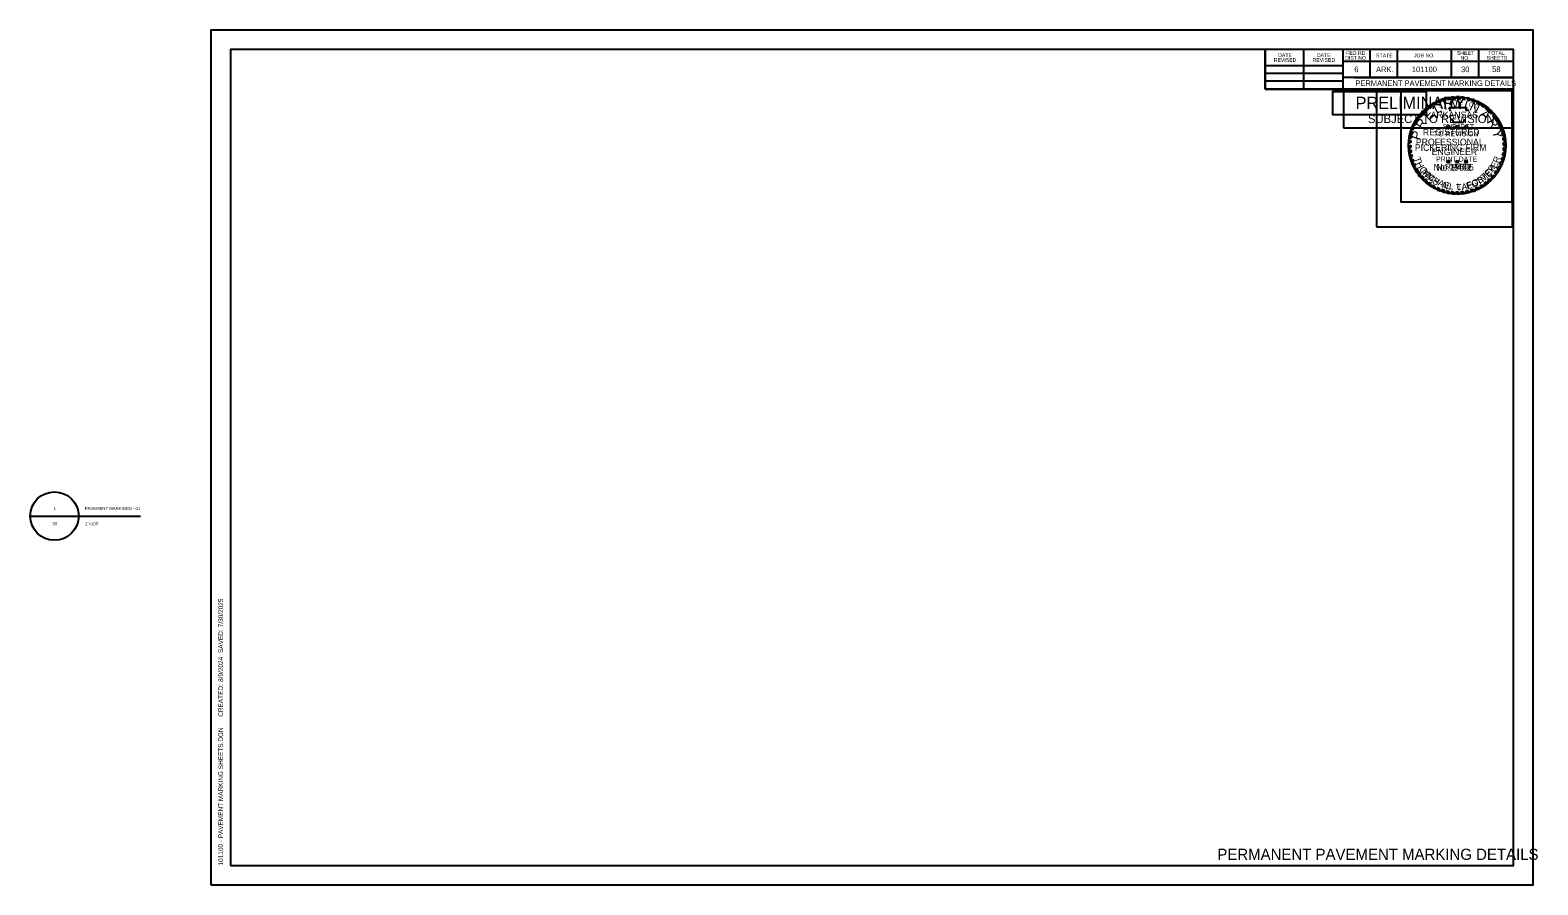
# Model space of a CAD drawing. Extents: x -0.19 to 1.42, y 0 to 0.92.
import ezdxf

# ---------------------------------------------------------------- set-up
doc = ezdxf.new("R2010")
doc.units = 0
for name, color, linetype in [('Default', 7, 'Continuous'), ('DSN_DRFT_Guideline-No-Plot', 7, 'Continuous'), ('SHET_Annotations', 7, 'Continuous'), ('SHET_Border-Lines', 7, 'Continuous'), ('SHET_Border-Text', 7, 'Continuous'), ('SHET_Stamp-Prelim', 7, 'Continuous'), ('SHET_Stamp-Seal', 7, 'Continuous'), ('STAMP_PE DIG SIG', 7, 'Continuous'), ('STAMP_PE_BACKGROUND', 7, 'Continuous'), ('STAMP_PE_FOSTER', 7, 'Continuous'), ('STAMP_PE_SEAL-INFO', 7, 'Continuous'), ('STAMP_PE_TAEGTMEYER', 7, 'Continuous'), ('STAMP_PRELIMINARY', 7, 'Continuous')]:
    doc.layers.add(name, color=color, linetype=linetype)

msp = doc.modelspace()

# ---------------------------------------------------------------- linework, layer by layer
at = {"layer": 'Default'}
for p, q in [((-0.1938, 0.3955), (-0.1417, 0.3955)), ((-0.1675, 0.3955), (-0.0755, 0.3955))]:
    msp.add_line(p, q, dxfattribs=at)
msp.add_circle((-0.1677, 0.3955), 0.026, dxfattribs=at)
at = {"layer": 'DSN_DRFT_Guideline-No-Plot'}
msp.add_lwpolyline([(0, 0), (1.4167, 0), (1.4167, 0.9167), (0, 0.9167)], close=True, dxfattribs=at)
at = {"layer": 'SHET_Border-Lines'}
for p, q in [((0.1176, 0.8988), (0.1176, 0.8988)), ((0.1176, 0.8988), (0.1176, 0.8988)), ((1.1296, 0.8534), (1.1296, 0.8958)), ((1.1711, 0.8534), (1.1711, 0.8958)), ((1.2127, 0.8958), (1.2127, 0.8534)), ((1.2417, 0.8958), (1.2417, 0.866)), ((1.2712, 0.8958), (1.2712, 0.866)), ((1.3289, 0.8958), (1.3289, 0.866)), ((1.3584, 0.8958), (1.3584, 0.866)), ((1.1296, 0.8786), (1.2127, 0.8786)), ((1.3958, 0.8832), (1.2127, 0.8832)), ((1.3958, 0.8833), (1.3958, 0.8833)), ((1.1296, 0.8706), (1.2127, 0.8706)), ((1.1296, 0.8622), (1.2127, 0.8622)), ((1.3958, 0.866), (1.2127, 0.866)), ((1.2252, 0.866), (1.3958, 0.866)), ((1.3958, 0.8534), (1.1296, 0.8534))]:
    msp.add_line(p, q, dxfattribs=at)
for points in [[(0.0208, 0.0208), (1.3958, 0.0208), (1.3958, 0.8958), (0.0208, 0.8958)], [(1.1296, 0.8534), (1.3958, 0.8534), (1.3958, 0.8958), (1.1296, 0.8958)]]:
    msp.add_lwpolyline(points, close=True, dxfattribs=at)
at = {"layer": 'SHET_Stamp-Prelim'}
msp.add_lwpolyline([(1.2137, 0.8119), (1.3948, 0.8119), (1.3948, 0.8524), (1.2137, 0.8524)], close=True, dxfattribs=at)
at = {"layer": 'SHET_Stamp-Seal'}
msp.add_line((1.3219, 0.7895), (1.3219, 0.7895), dxfattribs=at)
msp.add_lwpolyline([(1.249, 0.7057), (1.3948, 0.7057), (1.3948, 0.8524), (1.249, 0.8524)], close=True, dxfattribs=at)
at = {"layer": 'STAMP_PE DIG SIG'}
msp.add_lwpolyline([(1.2022, 0.8508), (1.3022, 0.8508), (1.3022, 0.8258), (1.2022, 0.8258)], close=True, dxfattribs=at)
at = {"layer": 'STAMP_PE_BACKGROUND'}
for points in [[(1.2022, 0.8517), (1.3022, 0.8517), (1.3022, 0.8258), (1.2022, 0.8258)], [(1.3942, 0.8517), (1.275, 0.8517), (1.275, 0.7325), (1.3942, 0.7325)]]:
    msp.add_lwpolyline(points, close=True, dxfattribs=at)
at = {"layer": 'STAMP_PE_SEAL-INFO'}
for p, q in [((1.3137, 0.8403), (1.3158, 0.8387)), ((1.3165, 0.8415), (1.3181, 0.8397)), ((1.3184, 0.8422), (1.3206, 0.8405)), ((1.3217, 0.8432), (1.3233, 0.8413)), ((1.3239, 0.8438), (1.3259, 0.8418)), ((1.3266, 0.8443), (1.3283, 0.8422)), ((1.3295, 0.8447), (1.331, 0.8426)), ((1.3336, 0.8427), (1.3318, 0.8449)), ((1.3364, 0.8428), (1.3348, 0.845)), ((1.3389, 0.8426), (1.3375, 0.845)), ((1.3417, 0.8424), (1.3401, 0.8448)), ((1.3441, 0.842), (1.3427, 0.8445)), ((1.3473, 0.8413), (1.3463, 0.8439)), ((1.3495, 0.8407), (1.3486, 0.8433)), ((1.352, 0.8399), (1.3512, 0.8426)), ((1.3544, 0.839), (1.3536, 0.8418)), ((1.357, 0.8379), (1.3564, 0.8406)), ((1.2946, 0.8253), (1.2977, 0.8254)), ((1.2965, 0.8276), (1.2994, 0.8274)), ((1.2983, 0.8295), (1.3014, 0.8293)), ((1.3002, 0.8313), (1.3028, 0.8306)), ((1.3021, 0.833), (1.3051, 0.8325)), ((1.3042, 0.8348), (1.3068, 0.8337)), ((1.3066, 0.8363), (1.309, 0.8352)), ((1.3087, 0.8377), (1.3112, 0.8365)), ((1.3112, 0.8391), (1.3138, 0.8378)), ((1.3269, 0.8337), (1.3456, 0.8337)), ((1.3276, 0.832), (1.3269, 0.8337)), ((1.3281, 0.8303), (1.3276, 0.832)), ((1.3282, 0.8297), (1.3281, 0.8303)), ((1.3456, 0.8337), (1.3443, 0.831)), ((1.3443, 0.831), (1.3478, 0.831)), ((1.3478, 0.831), (1.347, 0.8297)), ((1.3594, 0.8366), (1.359, 0.8394)), ((1.3616, 0.8353), (1.3614, 0.8381)), ((1.364, 0.8337), (1.3639, 0.8366)), ((1.366, 0.8322), (1.3662, 0.8349)), ((1.3685, 0.8301), (1.3687, 0.8331)), ((1.3703, 0.8285), (1.3707, 0.8313)), ((1.3723, 0.8264), (1.3727, 0.8294)), ((1.3738, 0.8247), (1.3746, 0.8273)), ((1.3756, 0.8223), (1.3764, 0.8251)), ((1.2853, 0.8071), (1.2879, 0.808)), ((1.2862, 0.8099), (1.2889, 0.8106)), ((1.287, 0.8121), (1.2898, 0.8129)), ((1.288, 0.8145), (1.2908, 0.8151)), ((1.2891, 0.8167), (1.2918, 0.8171)), ((1.2904, 0.8191), (1.2931, 0.8192)), ((1.2917, 0.8213), (1.2946, 0.8215)), ((1.293, 0.8232), (1.2959, 0.8232)), ((1.3252, 0.8129), (1.3241, 0.8137)), ((1.3241, 0.8137), (1.3255, 0.8137)), ((1.3248, 0.8116), (1.3252, 0.8129)), ((1.3259, 0.8124), (1.3248, 0.8116)), ((1.3255, 0.8137), (1.3259, 0.815)), ((1.3259, 0.815), (1.3264, 0.8137)), ((1.327, 0.8116), (1.3259, 0.8124)), ((1.3264, 0.8137), (1.3277, 0.8137)), ((1.3277, 0.8137), (1.3266, 0.8129)), ((1.3266, 0.8129), (1.327, 0.8116)), ((1.3293, 0.8201), (1.3291, 0.8213)), ((1.331, 0.8201), (1.3293, 0.8201)), ((1.331, 0.8177), (1.331, 0.8201)), ((1.3423, 0.8177), (1.331, 0.8177)), ((1.3347, 0.8129), (1.3336, 0.8137)), ((1.3336, 0.8137), (1.335, 0.8137)), ((1.3343, 0.8116), (1.3347, 0.8129)), ((1.3354, 0.8124), (1.3343, 0.8116)), ((1.335, 0.8137), (1.3354, 0.815)), ((1.3354, 0.815), (1.3358, 0.8137)), ((1.3365, 0.8116), (1.3354, 0.8124)), ((1.3358, 0.8137), (1.3372, 0.8137)), ((1.3372, 0.8137), (1.3361, 0.8129)), ((1.3361, 0.8129), (1.3365, 0.8116)), ((1.3424, 0.8196), (1.3423, 0.8177)), ((1.3429, 0.8213), (1.3424, 0.8196)), ((1.3442, 0.8129), (1.3431, 0.8137)), ((1.3431, 0.8137), (1.3445, 0.8137)), ((1.3438, 0.8116), (1.3442, 0.8129)), ((1.3449, 0.8124), (1.3438, 0.8116)), ((1.3445, 0.8137), (1.3449, 0.815)), ((1.3449, 0.815), (1.3453, 0.8137)), ((1.346, 0.8116), (1.3449, 0.8124)), ((1.3453, 0.8137), (1.3467, 0.8137)), ((1.3467, 0.8137), (1.3456, 0.8129)), ((1.3456, 0.8129), (1.346, 0.8116)), ((1.3769, 0.8206), (1.3779, 0.8232)), ((1.3786, 0.8178), (1.3796, 0.8205)), ((1.3797, 0.8157), (1.381, 0.8182)), ((1.381, 0.813), (1.3823, 0.8157)), ((1.3818, 0.8112), (1.3832, 0.8136)), ((1.3829, 0.8081), (1.3844, 0.8107)), ((1.3835, 0.8061), (1.3851, 0.8086)), ((1.2857, 0.796), (1.2834, 0.7946)), ((1.2856, 0.7933), (1.2834, 0.7914)), ((1.2859, 0.7984), (1.2835, 0.7968)), ((1.2862, 0.8008), (1.2838, 0.7996)), ((1.2867, 0.8034), (1.2841, 0.802)), ((1.2847, 0.8048), (1.2873, 0.8059)), ((1.3842, 0.8029), (1.386, 0.8054)), ((1.3846, 0.8008), (1.3866, 0.8028)), ((1.385, 0.798), (1.387, 0.7998)), ((1.3851, 0.7956), (1.3873, 0.7973)), ((1.3852, 0.7927), (1.3875, 0.7945)), ((1.3852, 0.7905), (1.3875, 0.792)), ((1.2857, 0.791), (1.2835, 0.7892)), ((1.2858, 0.7882), (1.2838, 0.7862)), ((1.2861, 0.7858), (1.2842, 0.7837)), ((1.2866, 0.7833), (1.2847, 0.7812)), ((1.2871, 0.7809), (1.2854, 0.7786)), ((1.2878, 0.7784), (1.2861, 0.7761)), ((1.2886, 0.7761), (1.287, 0.7738)), ((1.3252, 0.7754), (1.3241, 0.7763)), ((1.3241, 0.7763), (1.3255, 0.7763)), ((1.3255, 0.7763), (1.3259, 0.7776)), ((1.3259, 0.7776), (1.3264, 0.7763)), ((1.3264, 0.7763), (1.3277, 0.7763)), ((1.3277, 0.7763), (1.3266, 0.7754)), ((1.3347, 0.7754), (1.3336, 0.7763)), ((1.3336, 0.7763), (1.335, 0.7763)), ((1.335, 0.7763), (1.3354, 0.7776)), ((1.3354, 0.7776), (1.3358, 0.7763)), ((1.3358, 0.7763), (1.3372, 0.7763)), ((1.3372, 0.7763), (1.3361, 0.7754)), ((1.3442, 0.7754), (1.3431, 0.7763)), ((1.3431, 0.7763), (1.3445, 0.7763)), ((1.3445, 0.7763), (1.3449, 0.7776)), ((1.3449, 0.7776), (1.3453, 0.7763)), ((1.3453, 0.7763), (1.3467, 0.7763)), ((1.3467, 0.7763), (1.3456, 0.7754)), ((1.382, 0.7753), (1.3847, 0.776)), ((1.3827, 0.7774), (1.3855, 0.7785)), ((1.3835, 0.7802), (1.3862, 0.7813)), ((1.3841, 0.7827), (1.3867, 0.7838)), ((1.3846, 0.7855), (1.3871, 0.7867)), ((1.3849, 0.7876), (1.3874, 0.7891)), ((1.2895, 0.7737), (1.288, 0.7713)), ((1.2905, 0.7715), (1.2892, 0.769)), ((1.2918, 0.769), (1.2907, 0.7662)), ((1.2931, 0.7667), (1.2921, 0.7641)), ((1.2942, 0.765), (1.2936, 0.7619)), ((1.2958, 0.7628), (1.2952, 0.7598)), ((1.2975, 0.7607), (1.297, 0.7578)), ((1.3248, 0.7741), (1.3252, 0.7754)), ((1.3259, 0.7749), (1.3248, 0.7741)), ((1.327, 0.7741), (1.3259, 0.7749)), ((1.3266, 0.7754), (1.327, 0.7741)), ((1.3343, 0.7741), (1.3347, 0.7754)), ((1.3354, 0.7749), (1.3343, 0.7741)), ((1.3365, 0.7741), (1.3354, 0.7749)), ((1.3361, 0.7754), (1.3365, 0.7741)), ((1.3438, 0.7741), (1.3442, 0.7754)), ((1.3449, 0.7749), (1.3438, 0.7741)), ((1.346, 0.7741), (1.3449, 0.7749)), ((1.3456, 0.7754), (1.346, 0.7741)), ((1.3738, 0.7612), (1.3763, 0.7608)), ((1.3755, 0.7634), (1.3783, 0.7634)), ((1.3774, 0.7662), (1.3801, 0.7661)), ((1.3783, 0.7677), (1.3811, 0.768)), ((1.3799, 0.7705), (1.3826, 0.7709)), ((1.3808, 0.7724), (1.3835, 0.7729)), ((1.2992, 0.7588), (1.2988, 0.7559)), ((1.301, 0.757), (1.3008, 0.754)), ((1.3029, 0.7552), (1.3029, 0.7523)), ((1.3049, 0.7536), (1.305, 0.7507)), ((1.3068, 0.7522), (1.307, 0.7493)), ((1.3092, 0.7506), (1.3095, 0.7478)), ((1.3111, 0.7495), (1.3117, 0.7466)), ((1.3138, 0.7481), (1.3147, 0.7452)), ((1.3159, 0.7471), (1.3169, 0.7443)), ((1.3187, 0.7461), (1.3198, 0.7433)), ((1.321, 0.7453), (1.3222, 0.7426)), ((1.3238, 0.7445), (1.325, 0.7419)), ((1.326, 0.7441), (1.3274, 0.7415)), ((1.3288, 0.7436), (1.3302, 0.7411)), ((1.3313, 0.7433), (1.3328, 0.7409)), ((1.334, 0.7432), (1.3356, 0.7409)), ((1.3394, 0.7433), (1.3412, 0.7412)), ((1.3419, 0.7436), (1.344, 0.7416)), ((1.3444, 0.744), (1.3465, 0.7421)), ((1.3471, 0.7446), (1.3492, 0.7427)), ((1.3497, 0.7453), (1.352, 0.7436)), ((1.3524, 0.7462), (1.3549, 0.7447)), ((1.3548, 0.7471), (1.3571, 0.7456)), ((1.3573, 0.7483), (1.36, 0.7471)), ((1.3596, 0.7494), (1.3619, 0.7481)), ((1.3619, 0.7508), (1.3644, 0.7497)), ((1.3639, 0.7521), (1.3663, 0.751)), ((1.3664, 0.754), (1.369, 0.7532)), ((1.3679, 0.7553), (1.3706, 0.7545)), ((1.3702, 0.7573), (1.3727, 0.7566)), ((1.3716, 0.7588), (1.3743, 0.7583)), ((1.3365, 0.7432), (1.3384, 0.741))]:
    msp.add_line(p, q, dxfattribs=at)
for radius, start, end in [(0.0521, 111.3124, 114.7026), (0.0521, 105.2339, 109.0352), (0.0498, 104.0352, 107.3615), (0.0521, 99.7525, 102.7765), (0.0498, 98.258, 101.0329), (0.0521, 93.9381, 96.5517), (0.0498, 92.1102, 95.0367), (0.0521, 87.7298, 90.6707), (0.0498, 85.9628, 88.9097), (0.0521, 81.9732, 84.8236), (0.0498, 79.9264, 82.696), (0.0521, 75.3125, 77.9426), (0.0498, 73.5575, 76.2314), (0.0521, 69.6061, 72.3058), (0.0521, 63.1329, 66.2704), (0.0521, 141.6056, 144.4486), (0.0498, 139.301, 142.5873), (0.0521, 135.4021, 138.3031), (0.0498, 133.1331, 136.2562), (0.0521, 129.7326, 132.5376), (0.0498, 127.5297, 130.9683), (0.0521, 123.6199, 126.5906), (0.0498, 121.9746, 125.11), (0.0521, 117.6544, 120.8099), (0.0498, 115.6869, 119.1583), (0.0498, 110.3086, 113.1659), (0.0498, 67.6248, 70.504), (0.0498, 61.1558, 64.3784), (0.0521, 56.9003, 60.0942), (0.0498, 54.9238, 58.2702), (0.0498, 48.3016, 52.0395), (0.0521, 50.3492, 53.7159), (0.0498, 42.2212, 45.5512), (0.0521, 44.3405, 47.3929), (0.0498, 36.135, 39.5311), (0.0521, 38.1247, 41.2316), (0.0521, 158.4077, 161.0701), (0.0498, 162.4331, 165.0013), (0.0521, 152.864, 155.5189), (0.0498, 156.3402, 159.2319), (0.0521, 147.0072, 149.899), (0.0498, 151.0315, 153.573), (0.0498, 145.0197, 148.2104), (0.0498, 29.9032, 33.6645), (0.0521, 31.9614, 35.4294), (0.0498, 23.7732, 27.2211), (0.0521, 25.9391, 29.0125), (0.0498, 17.6802, 21.4251), (0.0521, 19.9538, 23.3141), (0.0521, 13.8421, 17.4447), (0.0521, 175.7409, 178.2066), (0.0521, 170.0003, 172.6878), (0.0521, 164.3068, 166.894), (0.0498, 179.6454, 182.2633), (0.0498, 173.73, 176.4734), (0.0498, 167.9048, 170.9039), (0.0498, 11.5444, 15.2364), (0.0498, 5.7599, 9.0606), (0.0498, 359.7329, 3.0639), (0.0521, 7.5852, 10.8621), (0.0521, 1.7215, 4.7268), (0.0521, 355.7156, 358.9569), (0.0521, 181.7251, 184.1626), (0.0521, 187.4204, 190.1927), (0.0521, 193.0369, 195.9973), (0.0498, 185.4539, 188.234), (0.0521, 198.8967, 201.6281), (0.0498, 191.2274, 193.9858), (0.0498, 196.9675, 199.8353), (0.0498, 341.777, 345.0925), (0.0521, 337.3837, 340.9933), (0.0498, 348.0778, 351.3435), (0.0498, 353.8632, 357.1274), (0.0521, 343.8925, 347.035), (0.0521, 349.8305, 353.0885), (0.0521, 204.5479, 207.4328), (0.0498, 202.7761, 205.4791), (0.0521, 210.8636, 213.6571), (0.0498, 208.7883, 211.7934), (0.0521, 216.6115, 219.491), (0.0498, 214.1838, 217.2747), (0.0498, 220.3909, 223.3056), (0.0498, 316.6531, 320.3711), (0.0521, 318.2846, 321.8043), (0.0498, 323.5851, 327.4407), (0.0498, 329.5549, 333.2076), (0.0521, 325.4405, 328.9872), (0.0498, 335.6038, 339.1858), (0.0521, 331.4037, 334.9332), (0.0521, 222.48, 225.3801), (0.0521, 228.3665, 231.348), (0.0498, 226.2494, 229.2407), (0.0498, 232.229, 234.9336), (0.0521, 234.295, 236.9452), (0.0498, 238.2223, 240.8353), (0.0521, 240.1977, 242.8613), (0.0498, 244.3204, 246.9486), (0.0521, 246.576, 249.1558), (0.0498, 250.3491, 253.1216), (0.0521, 252.5967, 255.3252), (0.0498, 256.505, 259.1192), (0.0498, 262.3783, 265.2012), (0.0498, 268.3215, 271.277), (0.0498, 274.6157, 277.4486), (0.0498, 280.3459, 283.5814), (0.0498, 286.6423, 289.9783), (0.0521, 288.5709, 291.9733), (0.0498, 292.8745, 296.1185), (0.0521, 294.6481, 298.2166), (0.0498, 299.0768, 302.1724), (0.0521, 300.621, 303.8703), (0.0498, 304.823, 308.5143), (0.0521, 306.3721, 310.208), (0.0498, 310.7744, 314.3161), (0.0521, 312.4518, 315.6633), (0.0521, 258.4433, 261.1398), (0.0521, 264.1978, 267.1009), (0.0521, 270.2548, 273.3361), (0.0521, 276.4239, 279.4357), (0.0521, 282.3199, 285.3702)]:
    msp.add_arc((1.3354, 0.793), radius, start, end, dxfattribs=at)
at = {"layer": 'STAMP_PRELIMINARY'}
msp.add_circle((1.3354, 0.793), 0.0521, dxfattribs=at)

# ---------------------------------------------------------------- texts
at = {"layer": 'Default'}
for s, height, p in [('1', 0.00328, (-0.1686, 0.4021)), ('PAVEMENT MARKINGS - 01', 0.003281, (-0.1352, 0.4021)), ('30', 0.00328, (-0.1699, 0.3857)), ('1"=100\'', 0.00328, (-0.1352, 0.3857))]:
    msp.add_text(s, height=height, dxfattribs=at).set_placement(p)
at = {"layer": 'SHET_Annotations'}
for s, height, p in [('6', 0.006, (1.2252, 0.8716)), ('ARK.', 0.006, (1.2485, 0.8716)), ('101100', 0.006, (1.2869, 0.8716)), ('30', 0.006, (1.3395, 0.8716)), ('58', 0.006, (1.3729, 0.8717)), ('PERMANENT PAVEMENT MARKING DETAILS', 0.006, (1.2264, 0.8567)), ('PERMANENT PAVEMENT MARKING DETAILS', 0.012, (1.0784, 0.0268))]:
    msp.add_text(s, height=height, dxfattribs=at).set_placement(p)
at = {"layer": 'SHET_Border-Text'}
for s, p in [('DATE', (1.1436, 0.8878)), ('DATE', (1.1851, 0.8878)), ('DIST.NO.', (1.2154, 0.8849)), ('FED.RD.', (1.2165, 0.8901)), ('STATE', (1.2485, 0.8875)), ('JOB NO.', (1.2891, 0.8875)), ('SHEET', (1.335, 0.8901)), ('NO.', (1.339, 0.8849)), ('SHEETS', (1.3668, 0.8849)), ('TOTAL', (1.3686, 0.8901)), ('REVISED', (1.1388, 0.8826)), ('REVISED', (1.1804, 0.8826))]:
    msp.add_text(s, height=0.004, dxfattribs=at).set_placement(p)
for s, p in [('7/30/2025', (0.0129, 0.2763)), ('  SAVED: ', (0.0129, 0.2448)), ('8/9/2024', (0.0129, 0.2177)), ('     CREATED: ', (0.0129, 0.1707)), ('101100 - PAVEMENT MARKING SHEETS.DGN', (0.0129, 0.0208))]:
    msp.add_text(s, height=0.005, rotation=90, dxfattribs=at).set_placement(p)
at = {"layer": 'SHET_Stamp-Prelim'}
for s, height, p in [('PRELIMINARY', 0.013, (1.2266, 0.8322)), ('SUBJECT TO REVISION', 0.009, (1.2398, 0.817))]:
    msp.add_text(s, height=height, dxfattribs=at).set_placement(p)
at = {"layer": 'STAMP_PE_FOSTER'}
for s, rotation, p in [('M', 308.339, (1.297, 0.7652)), ('I', 314.1842, (1.3014, 0.7599)), ('C', 319.8733, (1.3034, 0.7579)), ('S', 31.7234, (1.3588, 0.7517)), ('T', 39.4194, (1.3641, 0.7552)), ('E', 46.9613, (1.3689, 0.7594)), ('R', 54.5031, (1.373, 0.764)), ('H', 327.7235, (1.3086, 0.7538)), ('A', 335.7276, (1.3141, 0.7506)), ('E', 343.5779, (1.3204, 0.748)), ('L', 350.8115, (1.3263, 0.7464)), ('L', 1.2666, (1.3349, 0.7455)), ('.', 6.8035, (1.3408, 0.7459)), ('F', 15.8691, (1.3468, 0.7469)), ('O', 23.719, (1.3526, 0.7487))]:
    msp.add_text(s, height=0.0067, rotation=rotation, dxfattribs=at).set_placement(p)
msp.add_text('No. 9402', height=0.00698, dxfattribs=at).set_placement((1.313, 0.7661))
at = {"layer": 'STAMP_PE_SEAL-INFO'}
for s, rotation, p in [('A', 9.0679, (1.3269, 0.8361)), ('T', 1.8248, (1.3325, 0.8369)), ('E', 355.2002, (1.3375, 0.8369)), ('S', 23.5541, (1.3164, 0.8327)), ('T', 16.311, (1.3216, 0.8347)), ('O', 342.2506, (1.3472, 0.8354)), ('F', 335.0075, (1.3526, 0.8335))]:
    msp.add_text(s, height=0.00436, rotation=rotation, dxfattribs=at).set_placement(p)
for s, height, p in [('ARKANSAS', 0.00698, (1.3069, 0.8223)), ('REGISTERED', 0.00698, (1.2986, 0.8038)), ('PROFESSIONAL', 0.006983, (1.2911, 0.7932)), ('ENGINEER', 0.00698, (1.3081, 0.7826))]:
    msp.add_text(s, height=height, dxfattribs=at).set_placement(p)
at = {"layer": 'STAMP_PE_TAEGTMEYER'}
for s, rotation, p in [('T', 289.646, (1.289, 0.7791)), ('H', 296.7339, (1.291, 0.7736)), ('E', 63.0984, (1.377, 0.768)), ('R', 69.57, (1.3798, 0.7735)), ('O', 303.7708, (1.2943, 0.7674)), ('M', 314.2033, (1.298, 0.7621)), ('A', 321.0594, (1.3034, 0.7567)), ('M', 39.3, (1.3633, 0.7533)), ('E', 46.8094, (1.3692, 0.7582)), ('Y', 53.9986, (1.3733, 0.7628)), ('S', 327.8239, (1.308, 0.7531)), ('N', 344.2727, (1.3186, 0.7474)), ('.', 350.6464, (1.3254, 0.7456)), ('T', 3.0061, (1.3347, 0.7445)), ('A', 8.9826, (1.3405, 0.7448)), ('E', 17.6836, (1.3463, 0.7457)), ('G', 23.3052, (1.3522, 0.7475)), ('T', 31.466, (1.3583, 0.7503))]:
    msp.add_text(s, height=0.00698, rotation=rotation, dxfattribs=at).set_placement(p)
msp.add_text('No. 19605', height=0.00698, dxfattribs=at).set_placement((1.3101, 0.7661))
at = {"layer": 'STAMP_PRELIMINARY'}
for s, rotation, p in [('I', 12.5248, (1.3217, 0.8309)), ('M', 3.1074, (1.3278, 0.8326)), ('I', 342.3164, (1.3416, 0.833)), ('E', 42.3578, (1.3048, 0.8192)), ('L', 25.513, (1.3131, 0.8266)), ('N', 333.9382, (1.3478, 0.8315)), ('A', 315.6579, (1.3591, 0.8257)), ('P', 73.913, (1.2953, 0.7982)), ('R', 56.2292, (1.2984, 0.8095)), ('R', 301.3831, (1.3668, 0.8184)), ('Y', 283.2593, (1.3729, 0.8084))]:
    msp.add_text(s, height=0.0101, rotation=rotation, dxfattribs=at).set_placement(p)
for s, height, p in [('TO REVISION', 0.005363, (1.3105, 0.8028)), ('SUBJECT', 0.00536, (1.3198, 0.8106)), ('PICKERING FIRM', 0.006983, (1.29, 0.7872)), ('PRINT DATE', 0.00536, (1.3128, 0.7757)), ('$DATE$', 0.00536, (1.3222, 0.768))]:
    msp.add_text(s, height=height, dxfattribs=at).set_placement(p)

doc.saveas('drawing.dxf')
